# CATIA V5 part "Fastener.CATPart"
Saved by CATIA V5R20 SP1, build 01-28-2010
Part number: Fastener
Bounding box of the stored display mesh (mm): x -4.826 to 4.826, y -4.826 to 4.826, z -47.752 to 0
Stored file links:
  D:\v5_r20\psrt_files_downloaded\c13-catia-v5r20-prt\c13-catia-v5r20-figr-13-43\Part & Asm files\Fastener.CATPart
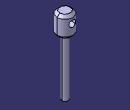
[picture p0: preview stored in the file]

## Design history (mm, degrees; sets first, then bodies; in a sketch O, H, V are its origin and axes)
Body1 (main body)
  Sketch1 on xy-plane, origin (0, 0, 0), H (1, 0, 0), V (0, 1, 0)
    circle A1 centre (0, 0) radius 4.826
    circle A2 centre (0, 0) radius 1.905
    radius A2 = 1.905
    radius A1 = 4.826
  MultiPad1: profile Sketch1, domains (length 0 / length 47.752; length 0 / length 12.7)
  Chamfer1: length 1.5875, angle 45, on 2 edges
  Chamfer2: length 0.508, angle 45, on 1 edge
  Sketch2 on zx-plane, origin (-1.612, 0, 1.612), H (1, 0, 0), V (0, 0, -1)
    point P1 (1.612, 6.35)
    reference intersected line E1 through (1.612, 0) direction (0, 1) from yz-plane
    distance P1 H = 6.35
    coincidence: E1 P1
  Hole1: placed by Sketch2, at (0, 0, -4.738) direction (0, -1, 0), diameter 4.064, depth 10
